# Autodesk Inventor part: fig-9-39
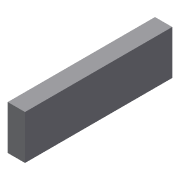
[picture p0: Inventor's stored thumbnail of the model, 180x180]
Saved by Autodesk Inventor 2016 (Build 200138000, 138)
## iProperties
Created: 2013-03
Part Number: fig-9-39
Material: Generic
Document SubType Name: Modeling
Designer: CADCIM
Density: 1 g/cm^3
Appearance: Default
Author: CADCIM
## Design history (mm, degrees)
sketch "Sketch1"
  geometry: L1 (-11.87, 2.655)-(7.31, 2.655); L2 (7.31, 2.655)-(7.31, -3.093); L3 (7.31, -3.093)-(-11.87, -3.093); L4 (-11.87, -3.093)-(-11.87, 2.655); 1 further point
  constraints: 8 end point, 2 parallel, 1 horizontal, 1 perpendicular
extrude "Extrusion1" new body sketch "Sketch1" distance "d0" = 2.25; taper "d1" = 0 deg
body "Solid1"
